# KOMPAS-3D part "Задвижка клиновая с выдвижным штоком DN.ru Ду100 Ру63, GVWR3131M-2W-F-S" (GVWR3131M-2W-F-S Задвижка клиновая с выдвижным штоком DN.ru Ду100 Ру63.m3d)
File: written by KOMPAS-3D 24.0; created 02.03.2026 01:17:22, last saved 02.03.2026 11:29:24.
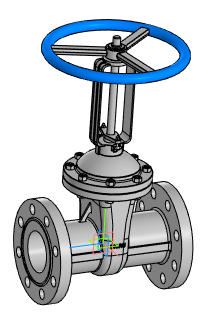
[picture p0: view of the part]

Document properties: Автор: R2D2; Полное имя файла: GVWR3131M-2W-F-S Задвижка клиновая с выдвижным штоком DN.ru Ду100 Ру63.cdw

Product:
- Part/product: Задвижка клиновая с выдвижным штоком DN.ru Ду100 Ру63  | designation GVWR3131M-2W-F-S
    Масса: 67
    Раздел спецификации: Прочие изделия
    Форматы листов документа: A2
    Примечание: D040-07395
    additional columns: D040-07395

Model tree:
1. Операция без истории:2

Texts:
  GVWR3131M-2W-F-S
